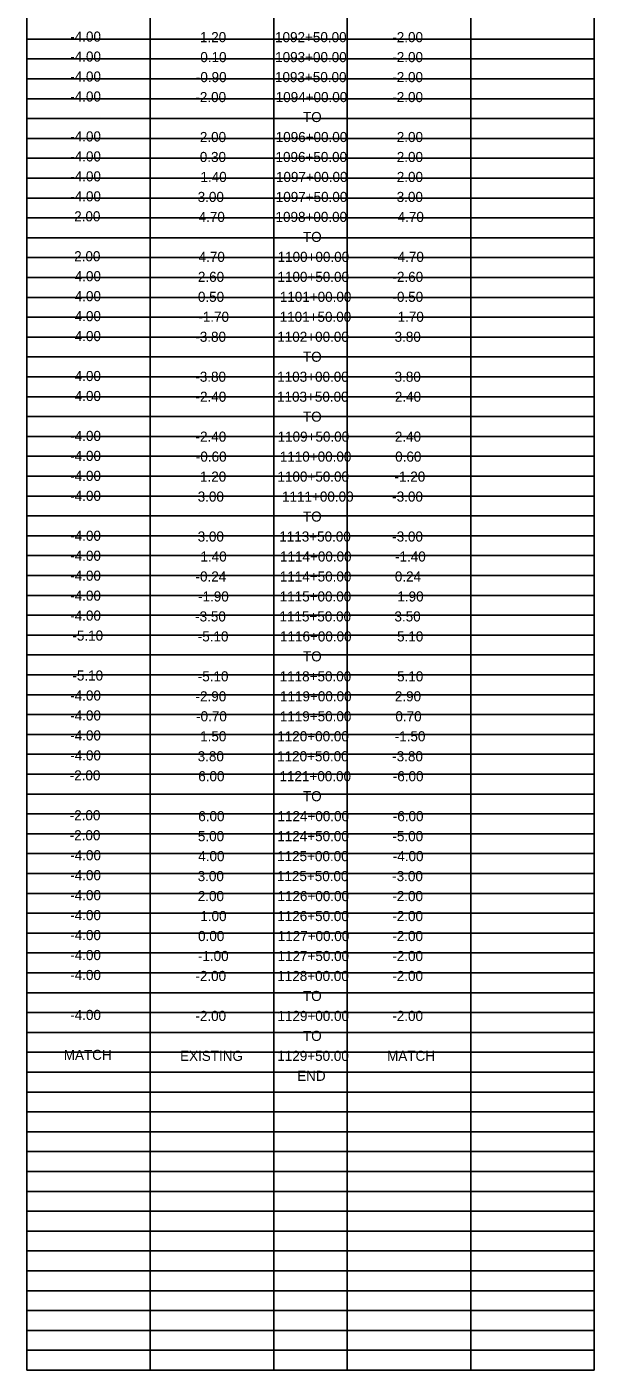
# Model space of a CAD drawing. Extents: x 1026502 to 1027102, y 781811 to 782040.
# Drawn here: x 1026801 to 1026828, y 781811.4 to 781875.3 of the extents above; entities that cross this region are included whole.
import ezdxf

# ---------------------------------------------------------------- set-up
doc = ezdxf.new("R2010")
doc.units = 0
doc.layers.add('BORDER', color=7, linetype='Continuous')
doc.layers.add('DIMENSIONS', color=7, linetype='Continuous')

msp = doc.modelspace()

# ---------------------------------------------------------------- linework, layer by layer
at = {"layer": 'BORDER'}
for p, q in [((1026801.005, 781879.462), (1026801.005, 781862.441)), ((1026806.888, 781879.462), (1026806.888, 781862.441)), ((1026812.771, 781879.462), (1026812.771, 781862.441)), ((1026816.271, 781879.462), (1026816.271, 781862.441)), ((1026822.154, 781879.462), (1026822.154, 781862.441)), ((1026828.037, 781879.462), (1026828.037, 781862.441)), ((1026801.005, 781874.734), (1026828.037, 781874.734)), ((1026801.005, 781873.789), (1026828.037, 781873.789)), ((1026801.005, 781872.843), (1026828.037, 781872.843)), ((1026801.005, 781871.897), (1026828.037, 781871.897)), ((1026801.005, 781870.952), (1026828.037, 781870.952)), ((1026801.005, 781870.006), (1026828.037, 781870.006)), ((1026801.005, 781869.061), (1026828.037, 781869.061)), ((1026801.005, 781868.115), (1026828.037, 781868.115)), ((1026801.005, 781867.169), (1026828.037, 781867.169)), ((1026801.005, 781866.224), (1026828.037, 781866.224)), ((1026801.005, 781865.278), (1026828.037, 781865.278)), ((1026801.005, 781864.333), (1026828.037, 781864.333)), ((1026801.005, 781863.387), (1026828.037, 781863.387)), ((1026801.005, 781862.441), (1026828.037, 781862.441)), ((1026801.005, 781862.441), (1026828.037, 781862.441)), ((1026801.005, 781862.441), (1026801.005, 781845.421)), ((1026806.888, 781862.441), (1026806.888, 781845.421)), ((1026812.771, 781862.441), (1026812.771, 781845.421)), ((1026816.271, 781862.441), (1026816.271, 781845.421)), ((1026822.154, 781862.441), (1026822.154, 781845.421)), ((1026828.037, 781862.441), (1026828.037, 781845.421)), ((1026801.005, 781861.496), (1026828.037, 781861.496)), ((1026801.005, 781860.55), (1026828.037, 781860.55)), ((1026801.005, 781859.605), (1026828.037, 781859.605)), ((1026801.005, 781858.659), (1026828.037, 781858.659)), ((1026801.005, 781857.713), (1026828.037, 781857.713)), ((1026801.005, 781856.768), (1026828.037, 781856.768)), ((1026801.005, 781855.822), (1026828.037, 781855.822)), ((1026801.005, 781854.877), (1026828.037, 781854.877)), ((1026801.005, 781853.931), (1026828.037, 781853.931)), ((1026801.005, 781852.985), (1026828.037, 781852.985)), ((1026801.005, 781852.04), (1026828.037, 781852.04)), ((1026801.005, 781851.094), (1026828.037, 781851.094)), ((1026801.005, 781850.149), (1026828.037, 781850.149)), ((1026801.005, 781849.203), (1026828.037, 781849.203)), ((1026801.005, 781848.257), (1026828.037, 781848.257)), ((1026801.005, 781847.312), (1026828.037, 781847.312)), ((1026801.005, 781846.366), (1026828.037, 781846.366)), ((1026801.005, 781845.421), (1026828.037, 781845.421)), ((1026801.005, 781845.421), (1026828.037, 781845.421)), ((1026801.005, 781845.421), (1026801.005, 781828.4)), ((1026806.888, 781845.421), (1026806.888, 781828.4)), ((1026812.771, 781845.421), (1026812.771, 781828.4)), ((1026816.271, 781845.421), (1026816.271, 781828.4)), ((1026822.154, 781845.421), (1026822.154, 781828.4)), ((1026828.037, 781845.421), (1026828.037, 781828.4)), ((1026801.005, 781844.475), (1026828.037, 781844.475)), ((1026801.005, 781843.529), (1026828.037, 781843.529)), ((1026801.005, 781842.584), (1026828.037, 781842.584)), ((1026801.005, 781841.638), (1026828.037, 781841.638)), ((1026801.005, 781840.693), (1026828.037, 781840.693)), ((1026801.005, 781839.747), (1026828.037, 781839.747)), ((1026801.005, 781838.801), (1026828.037, 781838.801)), ((1026801.005, 781837.856), (1026828.037, 781837.856)), ((1026801.005, 781836.91), (1026828.037, 781836.91)), ((1026801.005, 781835.965), (1026828.037, 781835.965)), ((1026801.005, 781835.019), (1026828.037, 781835.019)), ((1026801.005, 781834.073), (1026828.037, 781834.073)), ((1026801.005, 781833.128), (1026828.037, 781833.128)), ((1026801.005, 781832.182), (1026828.037, 781832.182)), ((1026801.005, 781831.237), (1026828.037, 781831.237)), ((1026801.005, 781830.291), (1026828.037, 781830.291)), ((1026801.005, 781829.345), (1026828.037, 781829.345)), ((1026801.005, 781828.4), (1026828.037, 781828.4)), ((1026801.005, 781828.4), (1026828.037, 781828.4)), ((1026801.005, 781828.4), (1026801.005, 781811.379)), ((1026806.888, 781828.4), (1026806.888, 781811.379)), ((1026812.771, 781828.4), (1026812.771, 781811.379)), ((1026816.271, 781828.4), (1026816.271, 781811.379)), ((1026822.154, 781828.4), (1026822.154, 781811.379)), ((1026828.037, 781828.4), (1026828.037, 781811.379)), ((1026801.005, 781827.454), (1026828.037, 781827.454)), ((1026801.005, 781826.509), (1026828.037, 781826.509)), ((1026801.005, 781825.563), (1026828.037, 781825.563)), ((1026801.005, 781824.617), (1026828.037, 781824.617)), ((1026801.005, 781823.672), (1026828.037, 781823.672)), ((1026801.005, 781822.726), (1026828.037, 781822.726)), ((1026801.005, 781821.781), (1026828.037, 781821.781)), ((1026801.005, 781820.835), (1026828.037, 781820.835)), ((1026801.005, 781819.889), (1026828.037, 781819.889)), ((1026801.005, 781818.944), (1026828.037, 781818.944)), ((1026801.005, 781817.998), (1026828.037, 781817.998)), ((1026801.005, 781817.053), (1026828.037, 781817.053)), ((1026801.005, 781816.107), (1026828.037, 781816.107)), ((1026801.005, 781815.161), (1026828.037, 781815.161)), ((1026801.005, 781814.216), (1026828.037, 781814.216)), ((1026801.005, 781813.27), (1026828.037, 781813.27)), ((1026801.005, 781812.325), (1026828.037, 781812.325)), ((1026801.005, 781811.379), (1026828.037, 781811.379))]:
    msp.add_line(p, q, dxfattribs=at)

# ---------------------------------------------------------------- texts
at = {"layer": 'DIMENSIONS'}
for s, p in [('-4.00', (1026803.073, 781874.616)), ('1.20', (1026809.255, 781874.59)), ('1092+50.00', (1026812.832, 781874.59)), ('-2.00', (1026818.419, 781874.59)), ('-4.00', (1026803.073, 781873.665)), ('0.10', (1026809.271, 781873.64)), ('1093+00.00', (1026812.836, 781873.64)), ('-2.00', (1026818.419, 781873.64)), ('-4.00', (1026803.073, 781872.715)), ('-0.90', (1026809.059, 781872.689)), ('1093+50.00', (1026812.829, 781872.689)), ('-2.00', (1026818.419, 781872.689)), ('-4.00', (1026803.073, 781871.764)), ('-2.00', (1026809.036, 781871.738)), ('1094+00.00', (1026812.863, 781871.738)), ('-2.00', (1026818.419, 781871.738)), ('TO', (1026814.162, 781870.787)), ('-4.00', (1026803.073, 781869.864)), ('-2.00', (1026809.036, 781869.836)), ('1096+00.00', (1026812.863, 781869.836)), ('-2.00', (1026818.419, 781869.836)), ('-4.00', (1026803.073, 781868.913)), ('-0.30', (1026809.033, 781868.885)), ('1096+50.00', (1026812.855, 781868.885)), ('-2.00', (1026818.419, 781868.885)), ('-4.00', (1026803.073, 781867.963)), ('1.40', (1026809.278, 781867.935)), ('1097+00.00', (1026812.874, 781867.935)), ('-2.00', (1026818.419, 781867.935)), ('-4.00', (1026803.073, 781867.012)), ('3.00', (1026809.146, 781866.984)), ('1097+50.00', (1026812.866, 781866.984)), ('-3.00', (1026818.415, 781866.984)), ('-2.00', (1026803.048, 781866.062)), ('4.70', (1026809.191, 781866.033)), ('1098+00.00', (1026812.855, 781866.033)), ('-4.70', (1026818.461, 781866.033)), ('TO', (1026814.162, 781865.082)), ('-2.00', (1026803.048, 781864.161)), ('4.70', (1026809.191, 781864.131)), ('1100+00.00', (1026812.953, 781864.131)), ('-4.70', (1026818.461, 781864.131)), ('-4.00', (1026803.073, 781863.211)), ('2.60', (1026809.157, 781863.18)), ('1100+50.00', (1026812.946, 781863.18)), ('-2.60', (1026818.427, 781863.18)), ('-4.00', (1026803.073, 781862.26)), ('0.50', (1026809.157, 781862.23)), ('1101+00.00', (1026813.059, 781862.23)), ('-0.50', (1026818.427, 781862.23)), ('-4.00', (1026803.073, 781861.31)), ('-1.70', (1026809.176, 781861.279)), ('1101+50.00', (1026813.052, 781861.279)), ('1.70', (1026818.672, 781861.279)), ('-4.00', (1026803.073, 781860.36)), ('-3.80', (1026809.033, 781860.328)), ('1102+00.00', (1026812.938, 781860.328)), ('3.80', (1026818.529, 781860.328)), ('TO', (1026814.162, 781859.377)), ('-4.00', (1026803.073, 781858.459)), ('-3.80', (1026809.033, 781858.426)), ('1103+00.00', (1026812.934, 781858.426)), ('3.80', (1026818.529, 781858.426)), ('-4.00', (1026803.073, 781857.508)), ('-2.40', (1026809.044, 781857.475)), ('1103+50.00', (1026812.927, 781857.475)), ('2.40', (1026818.54, 781857.475)), ('TO', (1026814.162, 781856.525)), ('-4.00', (1026803.073, 781855.608)), ('-2.40', (1026809.044, 781855.574)), ('1109+50.00', (1026812.953, 781855.574)), ('2.40', (1026818.54, 781855.574)), ('-4.00', (1026803.073, 781854.657)), ('-0.60', (1026809.059, 781854.623)), ('1110+00.00', (1026813.059, 781854.623)), ('0.60', (1026818.555, 781854.623)), ('-4.00', (1026803.073, 781853.707)), ('1.20', (1026809.255, 781853.672)), ('1100+50.00', (1026812.946, 781853.672)), ('-1.20', (1026818.525, 781853.672)), ('-4.00', (1026803.073, 781852.756)), ('3.00', (1026809.146, 781852.721)), ('1111+00.00', (1026813.165, 781852.721)), ('-3.00', (1026818.415, 781852.721)), ('TO', (1026814.162, 781851.77)), ('-4.00', (1026803.073, 781850.856)), ('3.00', (1026809.146, 781850.82)), ('1113+50.00', (1026813.033, 781850.82)), ('-3.00', (1026818.415, 781850.82)), ('-4.00', (1026803.073, 781849.905)), ('1.40', (1026809.278, 781849.869)), ('1114+00.00', (1026813.067, 781849.869)), ('-1.40', (1026818.548, 781849.869)), ('-4.00', (1026803.073, 781848.955)), ('-0.24', (1026809.044, 781848.918)), ('1114+50.00', (1026813.059, 781848.918)), ('0.24', (1026818.54, 781848.918)), ('-4.00', (1026803.073, 781848.004)), ('-1.90', (1026809.165, 781847.967)), ('1115+00.00', (1026813.052, 781847.967)), ('1.90', (1026818.661, 781847.967)), ('-4.00', (1026803.073, 781847.054)), ('-3.50', (1026809.025, 781847.016)), ('1115+50.00', (1026813.044, 781847.016)), ('3.50', (1026818.521, 781847.016)), ('-5.10', (1026803.176, 781846.104)), ('-5.10', (1026809.15, 781846.065)), ('1116+00.00', (1026813.067, 781846.065)), ('5.10', (1026818.646, 781846.065)), ('TO', (1026814.162, 781845.115)), ('-5.10', (1026803.176, 781844.203)), ('-5.10', (1026809.15, 781844.164)), ('1118+50.00', (1026813.052, 781844.164)), ('5.10', (1026818.646, 781844.164)), ('-4.00', (1026803.073, 781843.252)), ('-2.90', (1026809.044, 781843.213)), ('1119+00.00', (1026813.067, 781843.213)), ('2.90', (1026818.54, 781843.213)), ('-4.00', (1026803.073, 781842.302)), ('-0.70', (1026809.07, 781842.262)), ('1119+50.00', (1026813.059, 781842.262)), ('0.70', (1026818.566, 781842.262)), ('-4.00', (1026803.073, 781841.352)), ('1.50', (1026809.263, 781841.311)), ('1120+00.00', (1026812.938, 781841.311)), ('-1.50', (1026818.533, 781841.311)), ('-4.00', (1026803.073, 781840.401)), ('3.80', (1026809.146, 781840.36)), ('1120+50.00', (1026812.931, 781840.36)), ('-3.80', (1026818.415, 781840.36)), ('-2.00', (1026803.048, 781839.451)), ('6.00', (1026809.172, 781839.41)), ('1121+00.00', (1026813.044, 781839.41)), ('-6.00', (1026818.442, 781839.41)), ('TO', (1026814.162, 781838.459)), ('-2.00', (1026803.048, 781837.55)), ('6.00', (1026809.172, 781837.508)), ('1124+00.00', (1026812.946, 781837.508)), ('-6.00', (1026818.442, 781837.508)), ('-2.00', (1026803.048, 781836.6)), ('5.00', (1026809.157, 781836.557)), ('1124+50.00', (1026812.938, 781836.557)), ('-5.00', (1026818.427, 781836.557)), ('-4.00', (1026803.073, 781835.649)), ('4.00', (1026809.172, 781835.606)), ('1125+00.00', (1026812.931, 781835.606)), ('-4.00', (1026818.442, 781835.606)), ('-4.00', (1026803.073, 781834.699)), ('3.00', (1026809.146, 781834.655)), ('1125+50.00', (1026812.923, 781834.655)), ('-3.00', (1026818.415, 781834.655)), ('-4.00', (1026803.073, 781833.748)), ('2.00', (1026809.15, 781833.705)), ('1126+00.00', (1026812.946, 781833.705)), ('-2.00', (1026818.419, 781833.705)), ('-4.00', (1026803.073, 781832.798)), ('1.00', (1026809.271, 781832.754)), ('1126+50.00', (1026812.938, 781832.754)), ('-2.00', (1026818.419, 781832.754)), ('-4.00', (1026803.073, 781831.848)), ('0.00', (1026809.165, 781831.803)), ('1127+00.00', (1026812.957, 781831.803)), ('-2.00', (1026818.419, 781831.803)), ('-4.00', (1026803.073, 781830.897)), ('-1.00', (1026809.157, 781830.852)), ('1127+50.00', (1026812.949, 781830.852)), ('-2.00', (1026818.419, 781830.852)), ('-4.00', (1026803.073, 781829.947)), ('-2.00', (1026809.036, 781829.901)), ('1128+00.00', (1026812.938, 781829.901)), ('-2.00', (1026818.419, 781829.901)), ('TO', (1026814.162, 781828.95)), ('-4.00', (1026803.073, 781828.046)), ('-2.00', (1026809.036, 781828)), ('1129+00.00', (1026812.946, 781828)), ('-2.00', (1026818.419, 781828)), ('TO', (1026814.162, 781827.049)), ('MATCH', (1026802.764, 781826.145)), ('EXISTING', (1026808.306, 781826.098)), ('1129+50.00', (1026812.938, 781826.098)), ('MATCH', (1026818.169, 781826.098)), ('END', (1026813.886, 781825.147))]:
    msp.add_text(s, height=0.48, dxfattribs=at).set_placement(p)

doc.saveas('drawing.dxf')
